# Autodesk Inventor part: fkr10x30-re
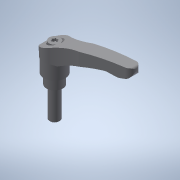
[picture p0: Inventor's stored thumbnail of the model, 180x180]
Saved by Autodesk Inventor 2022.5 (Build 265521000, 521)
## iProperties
Created: 2017-09
Part Number: fkr10x30-re
Material: 一般
Document SubType Name: Modeling
Designer: imaocorp
Density: 1 g/cm^3
Appearance: 既定
Author: imaocorp
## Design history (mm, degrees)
node "fkr10x30-re.x_t1"
node "fkr10x30-re"
node "Base1"
